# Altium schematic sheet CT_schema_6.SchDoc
size 368 x 245 mm
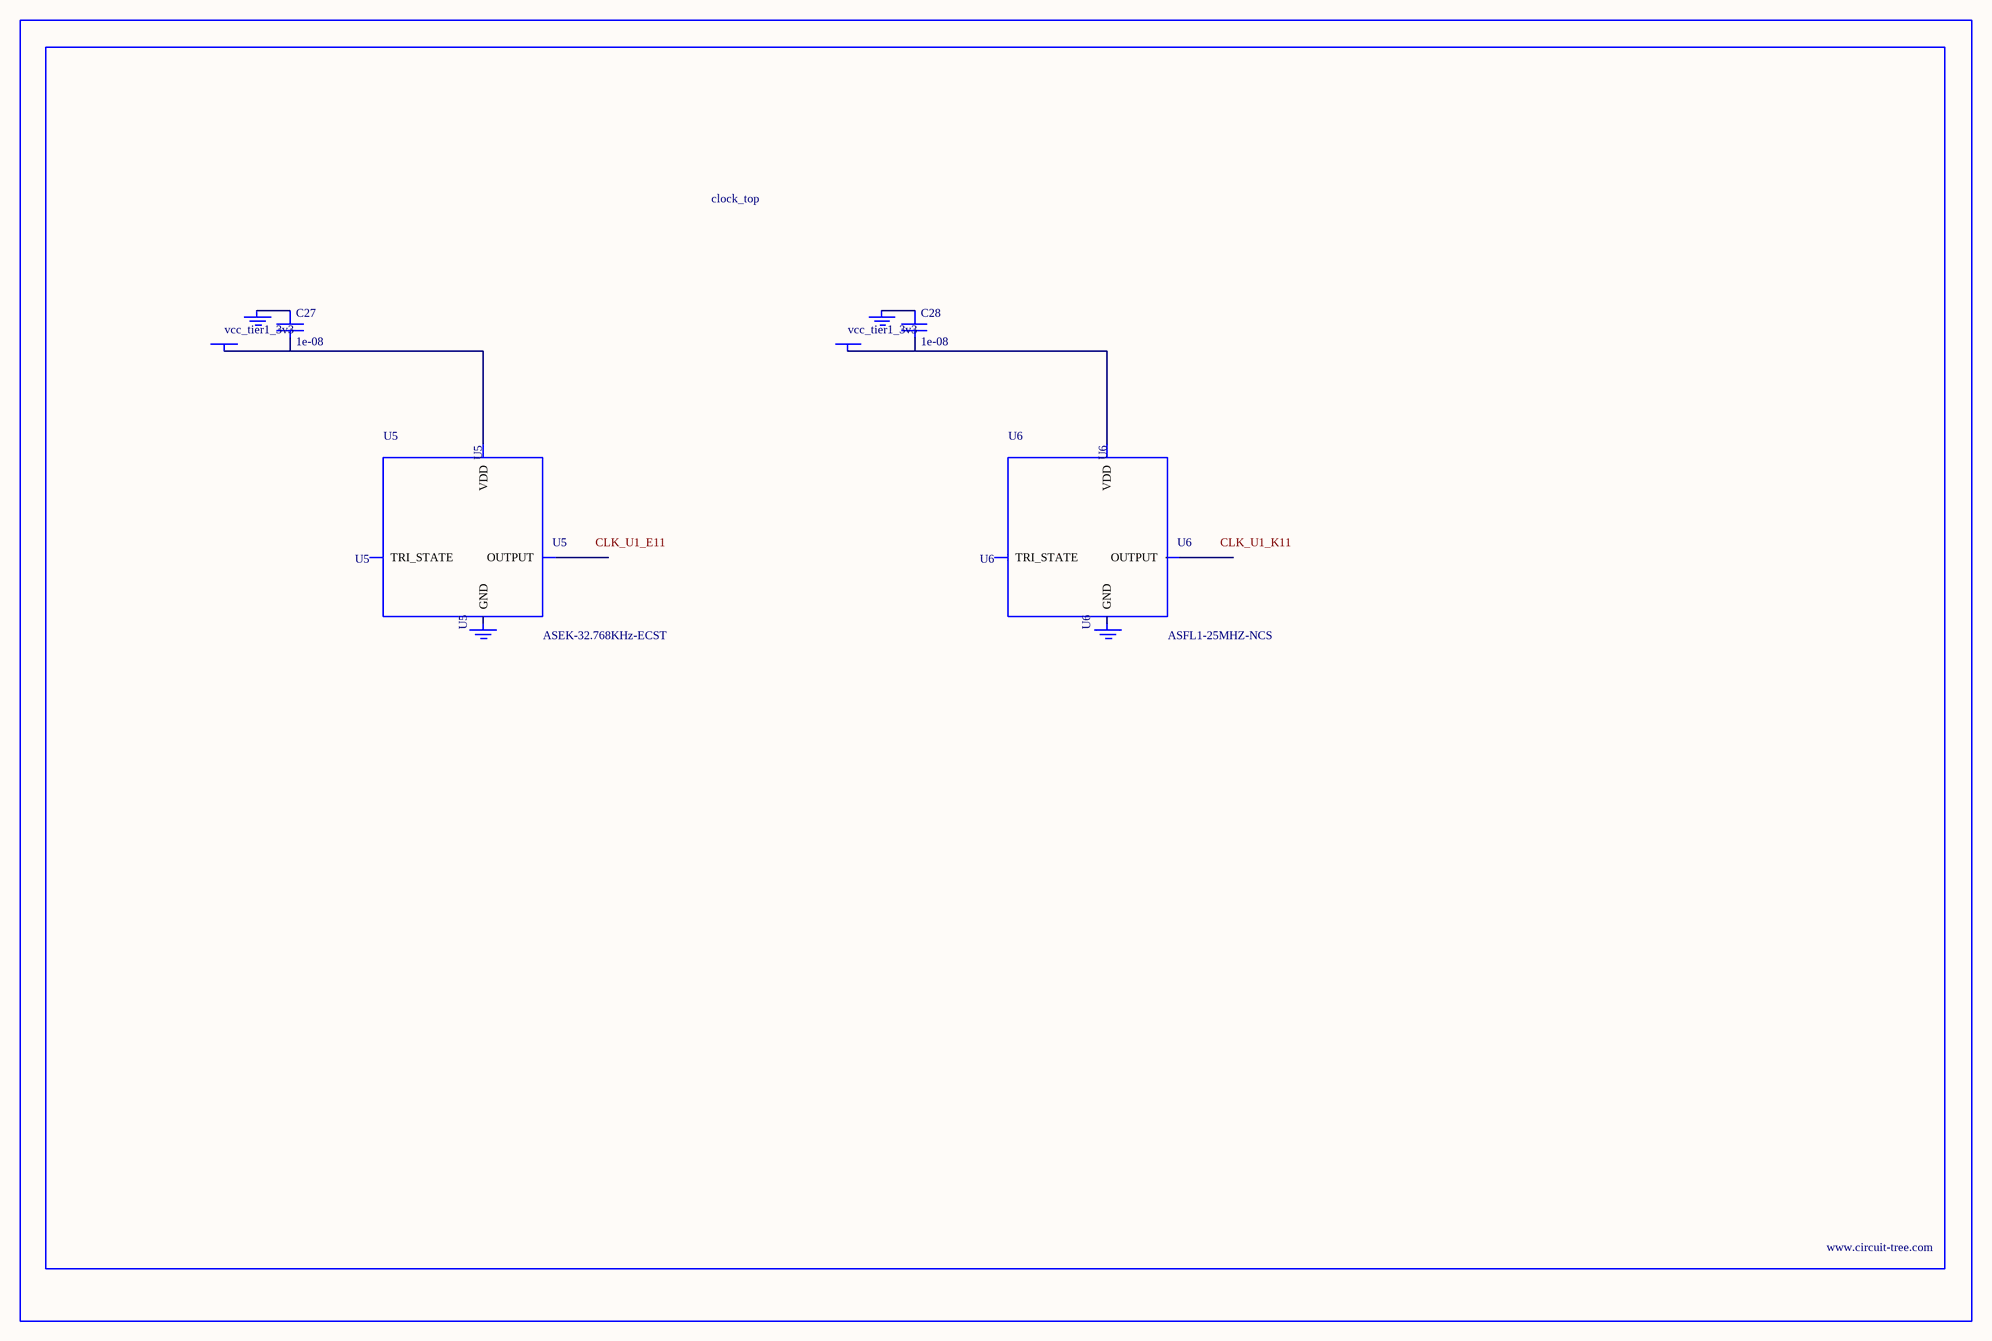
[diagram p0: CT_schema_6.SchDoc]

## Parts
BORDER5  (no value)
C27  1e-08  [C0402]
C28  1e-08  [C0402]
GND_INSTANCE_5_0  (no value)
GND_INSTANCE_5_1  (no value)
GND_INSTANCE_5_2  (no value)
GND_INSTANCE_5_3  (no value)
POWER_INSTANCE_5_0  vcc_tier1_3v3
POWER_INSTANCE_5_1  vcc_tier1_3v3
U5  ASEK-32.768KHz-ECST  [ASEK]
U6  ASFL1-25MHZ-NCS  [ASFL1]

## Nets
NetC27_1: C27.1 GND_INSTANCE_5_0.0(GND)
NetC27_2: C27.2 POWER_INSTANCE_5_0.0(PWR) U5.4(VDD)
NetC28_1: C28.1 GND_INSTANCE_5_2.0(GND)
NetC28_2: C28.2 POWER_INSTANCE_5_1.0(PWR) U6.4(VDD)

Not connected (* = marked no-connect by the designer): GND_INSTANCE_5_1 0(GND); GND_INSTANCE_5_3 0(GND); U5 1(TRI_STATE) 2(GND) 3(OUTPUT); U6 1(TRI_STATE) 2(GND) 3(OUTPUT)

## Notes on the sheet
- Labels drawn without touching a wire or pin: CLK_U1_E11, CLK_U1_K11

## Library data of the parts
BORDER5 = BORDER_PAGE5
C27 C28 = C0402C103K3RAC
GND_INSTANCE_5_0-GND_INSTANCE_5_3 = GND
POWER_INSTANCE_5_0 POWER_INSTANCE_5_1 = PWR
